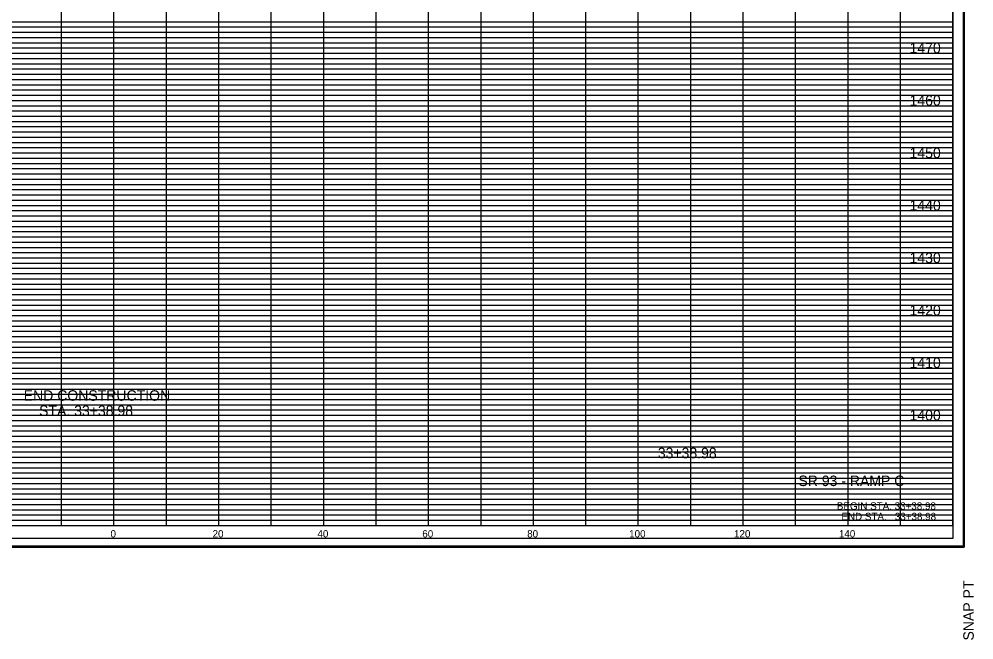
# Model space of a CAD drawing. Extents: x 980 to 2064, y 978 to 2267.
# Drawn here: x 1511.9 to 1694, y 1758.2 to 1876.5 of the extents above; entities that cross this region are included whole.
import ezdxf

# ---------------------------------------------------------------- set-up
doc = ezdxf.new("R2010")
doc.units = 0
for name, color, linetype in [('Default', 7, 'Continuous'), ('DESIGN - SHEET - Corner Text', 7, 'Continuous'), ('DESIGN - SHEET - Light Grid', 7, 'Continuous'), ('DESIGN - SHEET - Linework', 7, 'Continuous'), ('DESIGN - SHEET - Plot Shape', 7, 'Continuous'), ('DESIGN - TYPICAL - Text', 7, 'Continuous')]:
    doc.layers.add(name, color=color, linetype=linetype)

# ---------------------------------------------------------------- blocks, each defined once
blk = doc.blocks.new('XSTSHT')
at = {"layer": 'DESIGN - SHEET - Light Grid'}
for p, q in [((8, 9.6), (16, 9.6)), ((8, 9.5), (16, 9.5)), ((16, 9.6), (24, 9.6)), ((16, 9.5), (24, 9.5)), ((24, 9.6), (32, 9.6)), ((24, 9.5), (32, 9.5)), ((8, 9.4), (16, 9.4)), ((8, 9.3), (16, 9.3)), ((16, 9.4), (24, 9.4)), ((16, 9.3), (24, 9.3)), ((24, 9.4), (32, 9.4)), ((24, 9.3), (32, 9.3)), ((8, 9.2), (16, 9.2)), ((16, 9.2), (24, 9.2)), ((24, 9.2), (32, 9.2)), ((8, 9.1), (16, 9.1)), ((16, 9.1), (24, 9.1)), ((24, 9.1), (32, 9.1)), ((8, 8.9), (16, 8.9)), ((8, 8.8), (16, 8.8)), ((16, 8.9), (24, 8.9)), ((16, 8.8), (24, 8.8)), ((24, 8.9), (32, 8.9)), ((24, 8.8), (32, 8.8)), ((8, 8.7), (16, 8.7)), ((8, 8.6), (16, 8.6)), ((16, 8.7), (24, 8.7)), ((16, 8.6), (24, 8.6)), ((24, 8.7), (32, 8.7)), ((24, 8.6), (32, 8.6)), ((8, 8.5), (16, 8.5)), ((8, 8.4), (16, 8.4)), ((16, 8.5), (24, 8.5)), ((16, 8.4), (24, 8.4)), ((24, 8.5), (32, 8.5)), ((24, 8.4), (32, 8.4)), ((8, 8.3), (16, 8.3)), ((8, 8.2), (16, 8.2)), ((16, 8.3), (24, 8.3)), ((16, 8.2), (24, 8.2)), ((24, 8.3), (32, 8.3)), ((24, 8.2), (32, 8.2)), ((8, 8.1), (16, 8.1)), ((16, 8.1), (24, 8.1)), ((24, 8.1), (32, 8.1)), ((8, 7.9), (16, 7.9)), ((16, 7.9), (24, 7.9)), ((24, 7.9), (32, 7.9)), ((8, 7.8), (16, 7.8)), ((8, 7.7), (16, 7.7)), ((16, 7.8), (24, 7.8)), ((16, 7.7), (24, 7.7)), ((24, 7.8), (32, 7.8)), ((24, 7.7), (32, 7.7)), ((8, 7.6), (16, 7.6)), ((8, 7.5), (16, 7.5)), ((16, 7.6), (24, 7.6)), ((16, 7.5), (24, 7.5)), ((24, 7.6), (32, 7.6)), ((24, 7.5), (32, 7.5)), ((8, 7.4), (16, 7.4)), ((8, 7.3), (16, 7.3)), ((16, 7.4), (24, 7.4)), ((16, 7.3), (24, 7.3)), ((24, 7.4), (32, 7.4)), ((24, 7.3), (32, 7.3)), ((8, 7.2), (16, 7.2)), ((16, 7.2), (24, 7.2)), ((24, 7.2), (32, 7.2)), ((8, 7.1), (16, 7.1)), ((16, 7.1), (24, 7.1)), ((24, 7.1), (32, 7.1)), ((8, 6.9), (16, 6.9)), ((8, 6.8), (16, 6.8)), ((16, 6.9), (24, 6.9)), ((16, 6.8), (24, 6.8)), ((24, 6.9), (32, 6.9)), ((24, 6.8), (32, 6.8)), ((8, 6.7), (16, 6.7)), ((8, 6.6), (16, 6.6)), ((16, 6.7), (24, 6.7)), ((16, 6.6), (24, 6.6)), ((24, 6.7), (32, 6.7)), ((24, 6.6), (32, 6.6)), ((8, 6.5), (16, 6.5)), ((8, 6.4), (16, 6.4)), ((16, 6.5), (24, 6.5)), ((16, 6.4), (24, 6.4)), ((24, 6.5), (32, 6.5)), ((24, 6.4), (32, 6.4)), ((8, 6.3), (16, 6.3)), ((8, 6.2), (16, 6.2)), ((16, 6.3), (24, 6.3)), ((16, 6.2), (24, 6.2)), ((24, 6.3), (32, 6.3)), ((24, 6.2), (32, 6.2)), ((8, 6.1), (16, 6.1)), ((16, 6.1), (24, 6.1)), ((24, 6.1), (32, 6.1)), ((8, 5.9), (16, 5.9)), ((16, 5.9), (24, 5.9)), ((24, 5.9), (32, 5.9)), ((8, 5.8), (16, 5.8)), ((8, 5.7), (16, 5.7)), ((16, 5.8), (24, 5.8)), ((16, 5.7), (24, 5.7)), ((24, 5.8), (32, 5.8)), ((24, 5.7), (32, 5.7)), ((8, 5.6), (16, 5.6)), ((8, 5.5), (16, 5.5)), ((16, 5.6), (24, 5.6)), ((16, 5.5), (24, 5.5)), ((24, 5.6), (32, 5.6)), ((24, 5.5), (32, 5.5)), ((8, 5.4), (16, 5.4)), ((8, 5.3), (16, 5.3)), ((16, 5.4), (24, 5.4)), ((16, 5.3), (24, 5.3)), ((24, 5.4), (32, 5.4)), ((24, 5.3), (32, 5.3)), ((8, 5.2), (16, 5.2)), ((8, 5.1), (16, 5.1)), ((16, 5.2), (24, 5.2)), ((16, 5.1), (24, 5.1)), ((24, 5.2), (32, 5.2)), ((24, 5.1), (32, 5.1)), ((8, 4.9), (16, 4.9)), ((8, 4.8), (16, 4.8)), ((16, 4.9), (24, 4.9)), ((16, 4.8), (24, 4.8)), ((24, 4.9), (32, 4.9)), ((24, 4.8), (32, 4.8)), ((8, 4.7), (16, 4.7)), ((8, 4.6), (16, 4.6)), ((16, 4.7), (24, 4.7)), ((16, 4.6), (24, 4.6)), ((24, 4.7), (32, 4.7)), ((24, 4.6), (32, 4.6)), ((8, 4.5), (16, 4.5)), ((8, 4.4), (16, 4.4)), ((16, 4.5), (24, 4.5)), ((16, 4.4), (24, 4.4)), ((24, 4.5), (32, 4.5)), ((24, 4.4), (32, 4.4)), ((8, 4.3), (16, 4.3)), ((8, 4.2), (16, 4.2)), ((16, 4.3), (24, 4.3)), ((16, 4.2), (24, 4.2)), ((24, 4.3), (32, 4.3)), ((24, 4.2), (32, 4.2)), ((8, 4.1), (16, 4.1)), ((16, 4.1), (24, 4.1)), ((24, 4.1), (32, 4.1)), ((8, 3.9), (16, 3.9)), ((16, 3.9), (24, 3.9)), ((24, 3.9), (32, 3.9)), ((8, 3.8), (16, 3.8)), ((8, 3.7), (16, 3.7)), ((16, 3.8), (24, 3.8)), ((16, 3.7), (24, 3.7)), ((24, 3.8), (32, 3.8)), ((24, 3.7), (32, 3.7)), ((8, 3.6), (16, 3.6)), ((8, 3.5), (16, 3.5)), ((16, 3.6), (24, 3.6)), ((16, 3.5), (24, 3.5)), ((24, 3.6), (32, 3.6)), ((24, 3.5), (32, 3.5)), ((8, 3.4), (16, 3.4)), ((8, 3.3), (16, 3.3)), ((16, 3.4), (24, 3.4)), ((16, 3.3), (24, 3.3)), ((24, 3.4), (32, 3.4)), ((24, 3.3), (32, 3.3)), ((8, 3.2), (16, 3.2)), ((8, 3.1), (16, 3.1)), ((16, 3.2), (24, 3.2)), ((16, 3.1), (24, 3.1)), ((24, 3.2), (32, 3.2)), ((24, 3.1), (32, 3.1)), ((8, 2.9), (16, 2.9)), ((8, 2.8), (16, 2.8)), ((16, 2.9), (24, 2.9)), ((16, 2.8), (24, 2.8)), ((24, 2.9), (32, 2.9)), ((24, 2.8), (32, 2.8)), ((8, 2.7), (16, 2.7)), ((8, 2.6), (16, 2.6)), ((16, 2.7), (24, 2.7)), ((16, 2.6), (24, 2.6)), ((24, 2.7), (32, 2.7)), ((24, 2.6), (32, 2.6)), ((8, 2.5), (16, 2.5)), ((8, 2.4), (16, 2.4)), ((16, 2.5), (24, 2.5)), ((16, 2.4), (24, 2.4)), ((24, 2.5), (32, 2.5)), ((24, 2.4), (32, 2.4)), ((8, 2.3), (16, 2.3)), ((8, 2.2), (16, 2.2)), ((16, 2.3), (24, 2.3)), ((16, 2.2), (24, 2.2)), ((24, 2.3), (32, 2.3)), ((24, 2.2), (32, 2.2)), ((8, 2.1), (16, 2.1)), ((16, 2.1), (24, 2.1)), ((24, 2.1), (32, 2.1)), ((8, 1.9), (16, 1.9)), ((16, 1.9), (24, 1.9)), ((24, 1.9), (32, 1.9)), ((8, 1.8), (16, 1.8)), ((8, 1.7), (16, 1.7)), ((16, 1.8), (24, 1.8)), ((16, 1.7), (24, 1.7)), ((24, 1.8), (32, 1.8)), ((24, 1.7), (32, 1.7)), ((8, 1.6), (16, 1.6)), ((8, 1.5), (16, 1.5)), ((16, 1.6), (24, 1.6)), ((16, 1.5), (24, 1.5)), ((24, 1.6), (32, 1.6)), ((24, 1.5), (32, 1.5)), ((8, 1.4), (16, 1.4)), ((8, 1.3), (16, 1.3)), ((16, 1.4), (24, 1.4)), ((16, 1.3), (24, 1.3)), ((24, 1.4), (32, 1.4)), ((24, 1.3), (32, 1.3)), ((8, 1.2), (16, 1.2)), ((8, 1.1), (16, 1.1)), ((16, 1.2), (24, 1.2)), ((16, 1.1), (24, 1.1)), ((24, 1.2), (32, 1.2)), ((24, 1.1), (32, 1.1)), ((8, 0.9), (16, 0.9)), ((8, 0.8), (16, 0.8)), ((16, 0.9), (24, 0.9)), ((16, 0.8), (24, 0.8)), ((24, 0.9), (32, 0.9)), ((24, 0.8), (32, 0.8)), ((8, 0.7), (16, 0.7)), ((8, 0.6), (16, 0.6)), ((16, 0.7), (24, 0.7)), ((16, 0.6), (24, 0.6)), ((24, 0.7), (32, 0.7)), ((24, 0.6), (32, 0.6)), ((8, 0.5), (16, 0.5)), ((8, 0.4), (16, 0.4)), ((16, 0.5), (24, 0.5)), ((16, 0.4), (24, 0.4)), ((24, 0.5), (32, 0.5)), ((24, 0.4), (32, 0.4)), ((8, 0.3), (16, 0.3)), ((8, 0.2), (16, 0.2)), ((16, 0.3), (24, 0.3)), ((16, 0.2), (24, 0.2)), ((24, 0.3), (32, 0.3)), ((24, 0.2), (32, 0.2)), ((8, 0.1), (16, 0.1)), ((16, 0.1), (24, 0.1)), ((24, 0.1), (32, 0.1))]:
    blk.add_line(p, q, dxfattribs=at)
at = {"layer": 'DESIGN - SHEET - Linework'}
for p, q in [((32.217, 21.414), (32.217, -0.414)), ((15, 0), (15, 21)), ((16, 0), (16, 21)), ((17, 0), (17, 21)), ((18, 0), (18, 21)), ((19, 0), (19, 21)), ((20, 0), (20, 21)), ((21, 0), (21, 21)), ((22, 0), (22, 21)), ((23, 0), (23, 21)), ((24, 0), (24, 21)), ((25, 0), (25, 21)), ((26, 0), (26, 21)), ((27, 0), (27, 21)), ((28, 0), (28, 20)), ((29, 0), (29, 20)), ((30, 0), (30, 20)), ((31, 0), (31, 20)), ((0, 9), (32, 9)), ((0, 8), (32, 8)), ((0, 7), (32, 7)), ((0, 6), (32, 6)), ((0, 5), (32, 5)), ((0, 4), (32, 4)), ((0, 3), (32, 3)), ((0, 2), (32, 2)), ((0, 1), (32, 1)), ((-1.823, -0.414), (32.217, -0.414))]:
    blk.add_line(p, q, dxfattribs=at)
blk.add_lwpolyline([(0, 21), (0, 0), (32, 0), (32, 21), (0, 21)], dxfattribs=at)
at = {"layer": 'DESIGN - SHEET - Plot Shape'}
for points in [[(-1.803, 21.394), (32.197, 21.394), (32.197, -0.394), (-1.803, -0.394)], [(-0.85, 21), (32, 21), (32, -0.25), (-0.85, -0.25)]]:
    blk.add_lwpolyline(points, close=True, dxfattribs=at)
at = {"layer": 'DESIGN - SHEET - Corner Text'}
blk.add_text('SNAP PT  ', height=0.2, rotation=90, dxfattribs=at).set_placement((32.397, -2.194))

msp = doc.modelspace()

# ---------------------------------------------------------------- block references
at = {"layer": 'Default', "xscale": 10, "yscale": 10}
msp.add_blockref('XSTSHT', (1370, 1780), dxfattribs=at)

# ---------------------------------------------------------------- texts
at = {"layer": 'Default'}
for s, height, p in [('     1470     ', 2, (1678.01, 1870)), ('     1460     ', 2, (1678.01, 1860)), ('     1450     ', 2, (1678.01, 1850)), ('     1440     ', 2, (1678.01, 1840)), ('     1430     ', 2, (1678.01, 1830)), ('     1420     ', 2, (1678.01, 1820)), ('     1410     ', 2, (1678.01, 1810)), ('     1400     ', 2, (1678.01, 1800)), ('     33+38.98     ', 2, (1630, 1792.8)), ('     0     ', 1.4, (1526.74, 1777.7)), ('     0     ', 1.4, (1526.74, 1777.7)), ('     20     ', 1.4, (1546.2, 1777.7)), ('     40     ', 1.4, (1566.2, 1777.7)), ('     60     ', 1.4, (1586.2, 1777.7)), ('     80     ', 1.4, (1606.2, 1777.7)), ('     100     ', 1.4, (1625.65, 1777.7)), ('     120     ', 1.4, (1645.65, 1777.7)), ('     140     ', 1.4, (1665.65, 1777.7))]:
    msp.add_text(s, height=height, dxfattribs=at).set_placement(p)
at = {"layer": 'DESIGN - SHEET - Corner Text'}
for s, height, p in [('SR 93 - RAMP C', 2, (1660.53, 1787.5)), ('BEGIN STA. 33+38.98', 1.4, (1667.86, 1783)), ('END STA.   33+38.98', 1.4, (1668.73, 1781))]:
    msp.add_text(s, height=height, dxfattribs=at).set_placement(p)
at = {"layer": 'DESIGN - TYPICAL - Text'}
for s, p in [('END CONSTRUCTION', (1512.78, 1803.76)), ('STA. 33+38.98', (1515.72, 1800.86))]:
    msp.add_text(s, height=2, dxfattribs=at).set_placement(p)

doc.saveas('drawing.dxf')
